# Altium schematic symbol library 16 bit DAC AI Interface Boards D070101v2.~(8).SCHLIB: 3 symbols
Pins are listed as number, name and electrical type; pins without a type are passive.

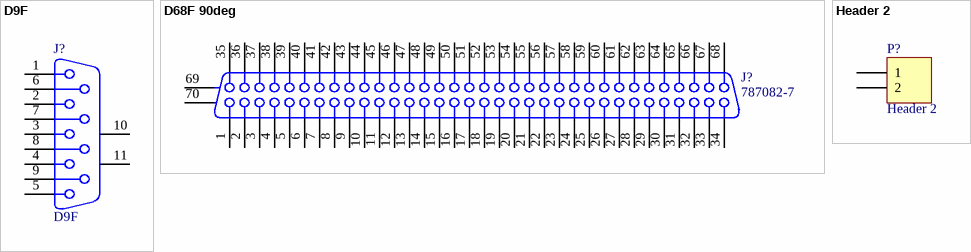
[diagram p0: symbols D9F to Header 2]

## D9F
designator J?
9 Position D-Sub Receptacle, Female Sockets Connector; Manufacturer: TE Connectivity; Manufacturer Part Number: 5747150-7; Description: CONN D-SUB RCPT 9POS VERT SOLDER; Plating: Tin; Body Material: Metal; Voltage Rating: 125V; Current Rating: 6A; Max Voltage Rating (DC): 250.25kV; Number of Positions: 9; Number of Ports: 1; Max Supply Voltage (AC): 250V; Mating Connector Lock: Yes (With); PCB Mount Retention: With; PCB Mounting Orientation: Vertical; Preloaded: Yes; Sealable: No (Without); Pitch: 0.108inch; PCB Thickness: 2.36mm; Contact Post Length: 0.125inch; Hole Diameter: 0.12inch; Approvals: UL
footprint D9F
pins: 1, 2, 3, 4, 5, 6, 7, 8, 9, 10 MH1, 11 MH2

## D68F 90deg
designator J?, comment 787082-7
68 Position D-Type Receptacle, Female Sockets Connector; Manufacturer: TE Connectivity; Manufacturer Part Number: 7870827; Plating: Bright,Copper; Voltage Rating: 30V; Current Rating: 1A; Number of Positions: 68; Connector Type: Receptacle,Connector; Number of Ports: 1; Shielding: Shielded; Mating Alignment: No (Without); Mating Connector Lock: Yes (With); PCB Mount Retention: With; PCB Mounting Orientation: Right Angle; Pitch: 0.05inch; PCB Thickness: 1.57mm; Contact Post Length: 0.1inch; Hole Diameter: 0.109inch; Approvals: UL
footprint 787082-7 (Connector; D Subminiature 050 Series; 68 Position; Right Angle)
signal-integrity model D Subminiature
pins: 1, 2, 3, 4, 5, 6, 7, 8, 9, 10, 11, 12, 13, 14, 15, 16, 17, 18, 19, 20, 21, 22, 23, 24, 25, 26, 27, 28, 29, 30, 31, 32, 33, 34, 35, 36, 37, 38, 39, 40, 41, 42, 43, 44, 45, 46, 47, 48, 49, 50, 51, 52, 53, 54, 55, 56, 57, 58, 59, 60, 61, 62, 63, 64, 65, 66, 67, 68, 69 MH1, 70 MH2

## Header 2
designator P?
Connector Header Through Hole 2 position 0.100" (2.54mm); Manufacturer: Molex; Number of Positions: 2; Gender: Male; Contact Resistance: 10mR; Max Current Rating: 4A; Voltage Rating: 250V; Insulation Resistance: 500GR; Approvals: UL,CSA; Glow Wire Compliant: Non-compliant
footprint HDR1X2 (Connector; Header; 2 Position)
signal-integrity model Connector
pins: 1, 2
